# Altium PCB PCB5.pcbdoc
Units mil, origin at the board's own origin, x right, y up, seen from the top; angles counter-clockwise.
Board outline 5165.36 x 3350.39 mil, 2 copper layers (Top Layer, Bottom Layer); 78 components, 67 nets, 251 pads, 85 vias.
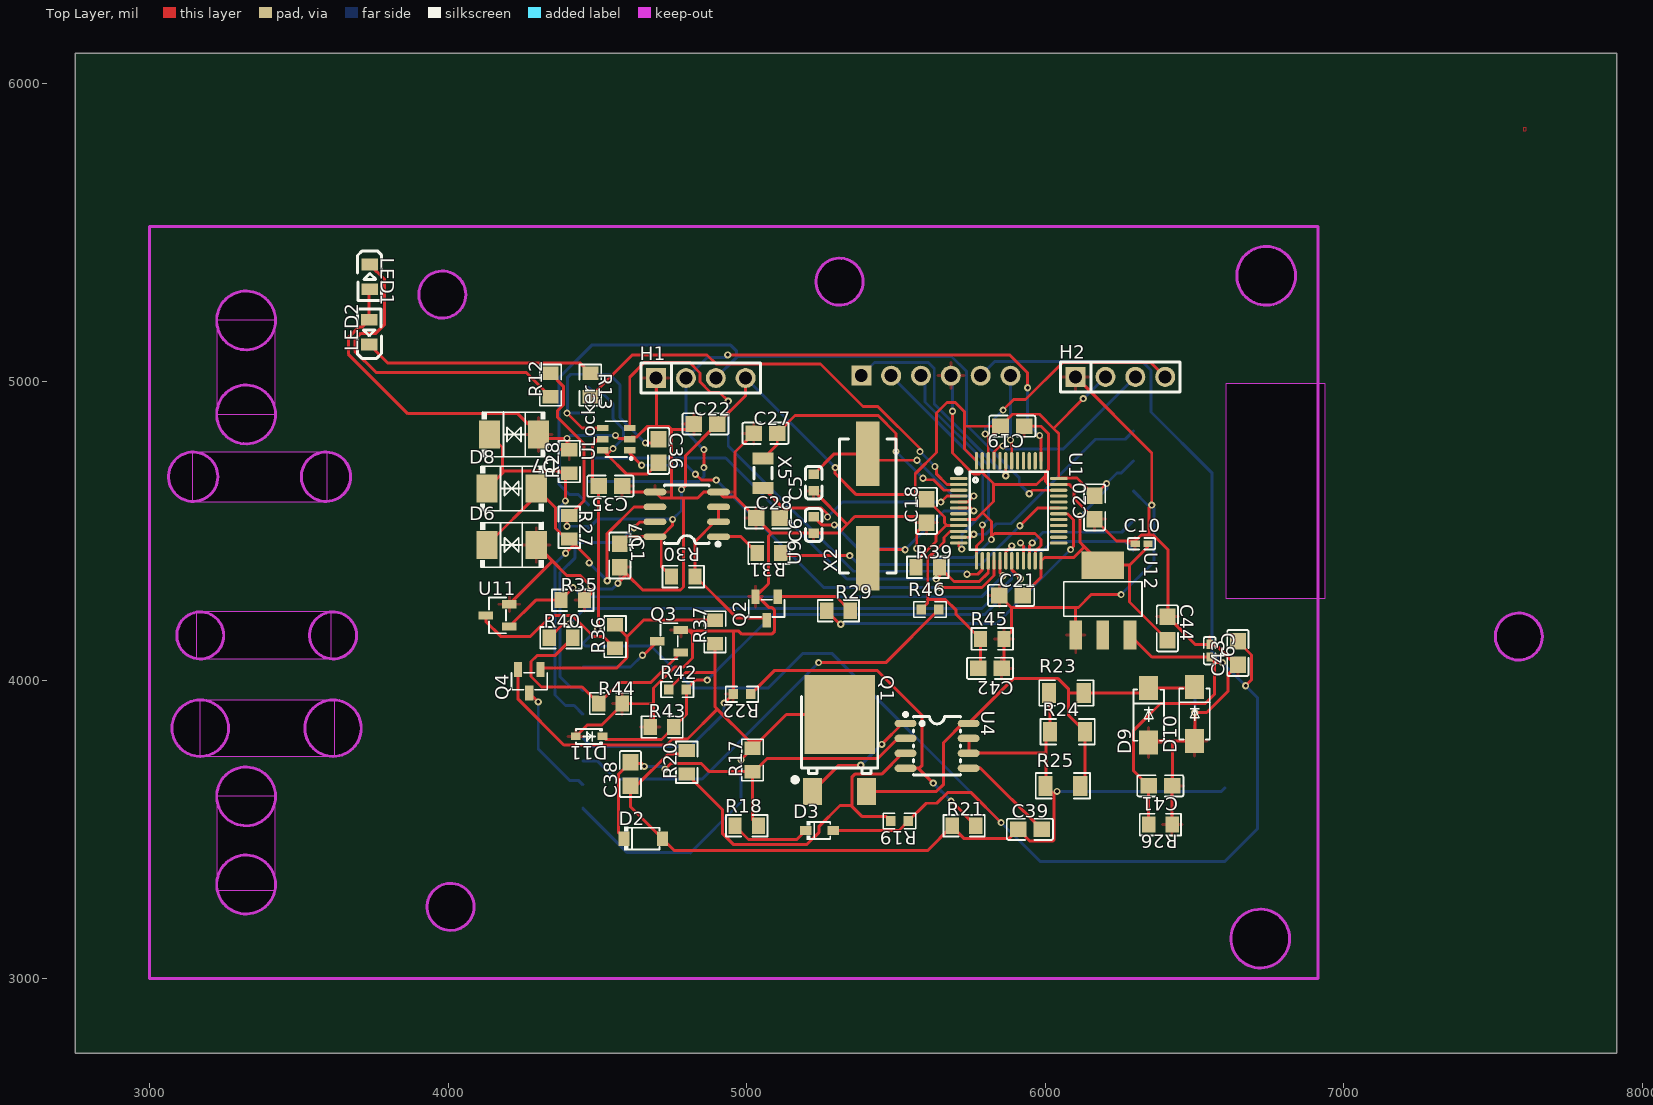
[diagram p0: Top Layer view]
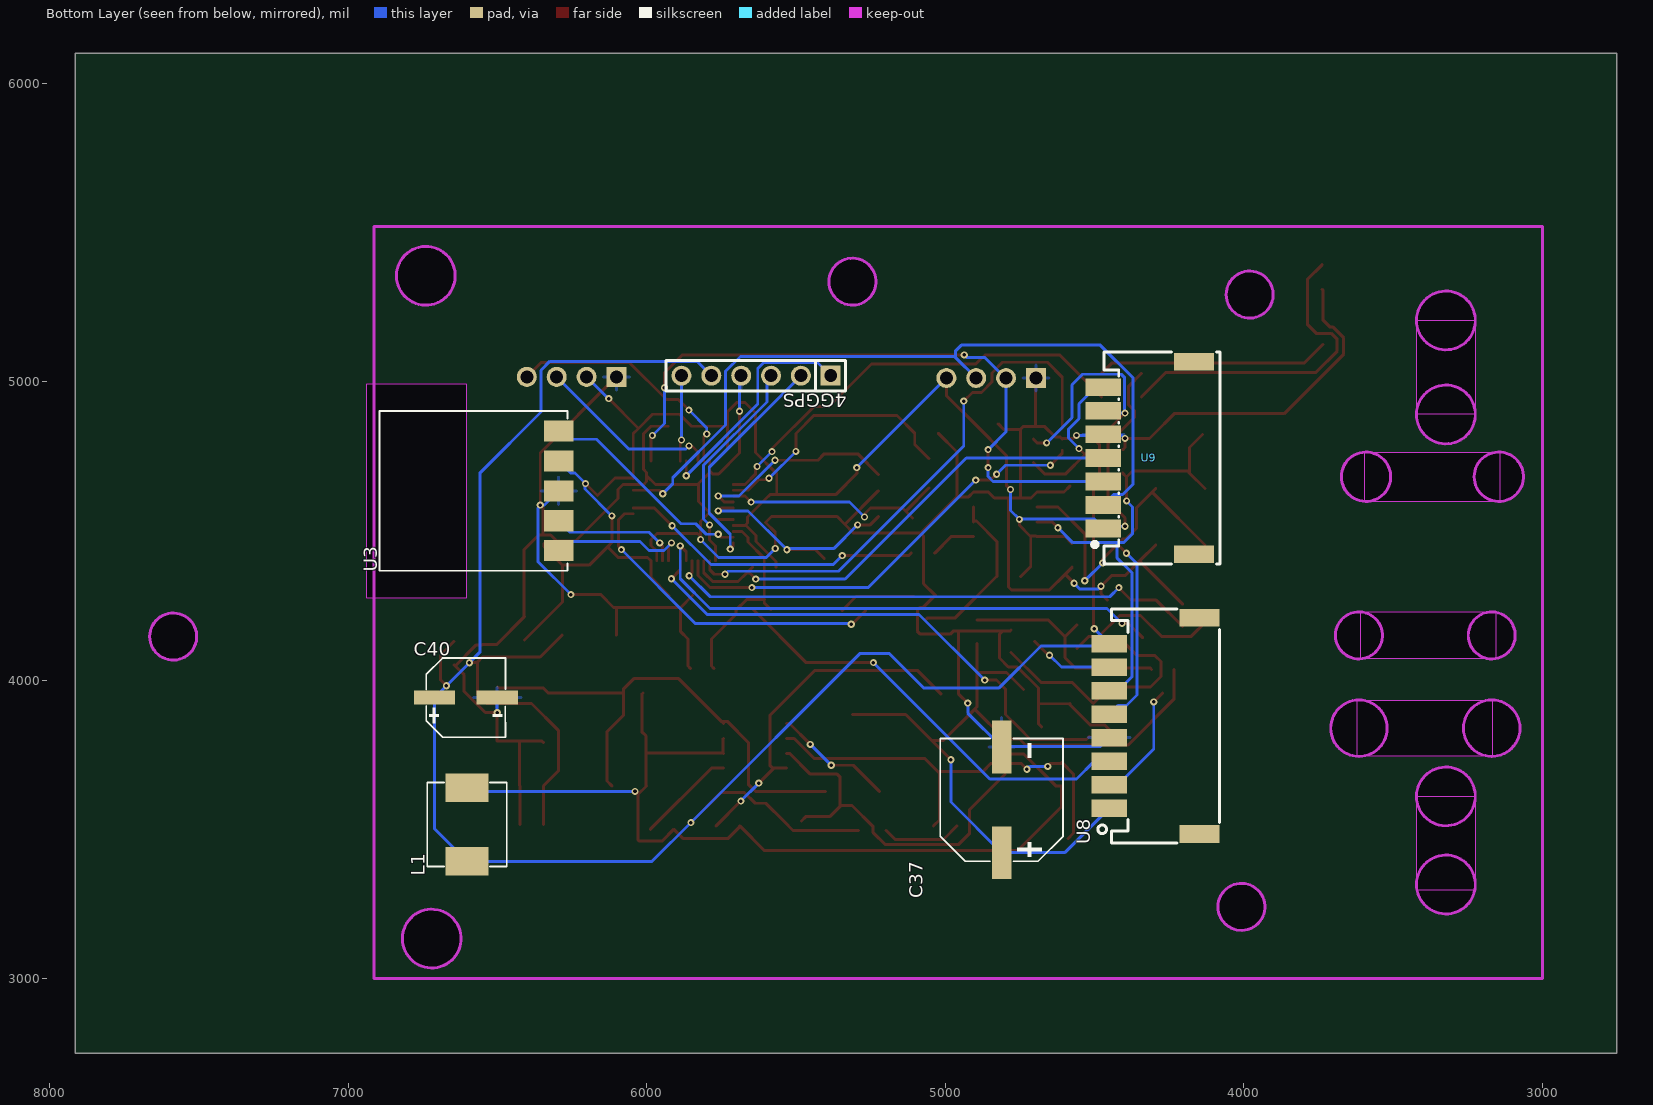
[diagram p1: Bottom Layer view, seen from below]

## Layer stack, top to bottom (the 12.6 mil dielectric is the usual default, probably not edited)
Top Layer: signal copper (thickness not stored)
Dielectric: dielectric 12.6, FR-4, Dk 4.8
Bottom Layer: signal copper (thickness not stored)

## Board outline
7915.36,2750 2750,2750 2750,6100.39 7915.36,6100.39
cut-out: 3421.26,4889.76 ccw(c3322.84,4889.56) 3224.41,4889.76 ccw(c3322.84,4889.96)
cut-out: 3421.26,3610.24 ccw(c3322.84,3610.04) 3224.41,3610.24 ccw(c3322.84,3610.44)
cut-out: 3421.26,5204.72 ccw(c3322.83,5204.48) 3224.41,5204.72 ccw(c3322.83,5204.97)
cut-out: 3421.26,3314.96 ccw(c3322.83,3314.72) 3224.41,3314.96 ccw(c3322.83,3315.2)
cut-out: 3673.23,4681.1 ccw(c3590.55,4681.1) 3507.87,4681.1 ccw(c3590.55,4681.1)
cut-out: 3692.91,4149.61 ccw(c3614.17,4149.61) 3535.43,4149.61 ccw(c3614.17,4149.61)
cut-out: 3708.66,3838.58 ccw(c3614.18,3837.9) 3519.69,3838.58 ccw(c3614.18,3839.26)
cut-out: 3228.35,4681.1 ccw(c3145.67,4681.1) 3062.99,4681.1 ccw(c3145.67,4681.1)
cut-out: 3263.78,3838.58 ccw(c3169.29,3838.58) 3074.8,3838.58 ccw(c3169.29,3838.58)
cut-out: 3248.03,4149.61 ccw(c3169.29,4149.61) 3090.55,4149.61 ccw(c3169.29,4149.61)
cut-out: 6838.58,5354.33 ccw(c6740.16,5354.33) 6641.73,5354.33 ccw(c6740.16,5354.33)
cut-out: 6818.9,3133.86 ccw(c6720.47,3133.6) 6622.05,3133.86 ccw(c6720.47,3134.12)
cut-out: 4059.06,5291.34 ccw(c3980.32,5290.73) 3901.58,5291.34 ccw(c3980.32,5291.95)
cut-out: 4086.61,3240.16 ccw(c4007.87,3240.16) 3929.13,3240.16 ccw(c4007.87,3240.16)
cut-out: 7665.36,4145.67 ccw(c7586.62,4145.14) 7507.88,4145.67 ccw(c7586.62,4146.19)
cut-out: 5389.77,5334.65 ccw(c5311.02,5334.65) 5232.28,5334.65 ccw(c5311.02,5334.65)
cut-out: 3224.41,4889.76 3421.26,4889.76 3421.26,5204.72 3224.41,5204.72
cut-out: 3224.41,3295.28 3421.26,3295.28 3421.26,3610.24 3224.41,3610.24
cut-out: 3141.73,4597.91 3594.49,4597.91 3594.49,4763.37 3141.73,4763.37
cut-out: 3155.51,4070.82 3608.27,4070.82 3608.27,4228.4 3155.51,4228.4
cut-out: 3167.32,3744.04 3620.08,3744.04 3620.08,3933.12 3167.32,3933.12
cut-out: 6604.87,4273.8 6938.98,4273.8 6938.98,4993.12 6604.87,4993.12

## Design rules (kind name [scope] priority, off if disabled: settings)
Clearance copperThickness1oz [All] p1: gap=7 ignorepadtopadclearanceinfootprint=FALSE except(4: Track-Track; 6: Track-SMDPad SMDPad-SMDPad Track-THPad SMDPad-THPad THPad-THPad Track-Via SMDPad-Via THPad-Via Via-Via SMDPad-Fill THPad-Fill Via-Fill Fill-Fill Track-Region SMDPad-Region THPad-Region Via-Region Region-Region Track-Poly SMDPad-Poly THPad-Poly Via-Poly Fill-Poly Region-Poly Poly-Poly Track-Text SMDPad-Text THPad-Text Via-Text Fill-Text Region-Text Poly-Text Text-Text; 6.9: Track-Hole SMDPad-Hole THPad-Hole Via-Hole Fill-Hole Region-Hole Poly-Hole Text-Hole Sheet-Hole; 11.8: Track-Fill Fill-Region Track-Sheet SMDPad-Sheet THPad-Sheet Via-Sheet Fill-Sheet Region-Sheet Poly-Sheet Text-Sheet)
Clearance copperThickness2oz [All] p1: gap=7 ignorepadtopadclearanceinfootprint=FALSE except(6: Track-SMDPad SMDPad-SMDPad Track-THPad SMDPad-THPad THPad-THPad Track-Via SMDPad-Via THPad-Via Via-Via SMDPad-Fill THPad-Fill Via-Fill Fill-Fill Track-Region SMDPad-Region THPad-Region Via-Region Region-Region Track-Poly SMDPad-Poly THPad-Poly Via-Poly Fill-Poly Region-Poly Poly-Poly Track-Text SMDPad-Text THPad-Text Via-Text Fill-Text Region-Text Poly-Text Text-Text; 6.9: Track-Hole SMDPad-Hole THPad-Hole Via-Hole Fill-Hole Region-Hole Poly-Hole Text-Hole Sheet-Hole; 8: Track-Track; 11.8: Track-Fill Fill-Region Track-Sheet SMDPad-Sheet THPad-Sheet Via-Sheet Fill-Sheet Region-Sheet Poly-Sheet Text-Sheet)
DiffPairsRouting differentialPair [All] p1: maxuncoupledlength=10 maxlimit=5.9843 mostfreqgap=5.9843 toplayer_minwidth=5 toplayer_prefwidth=10 toplayer_maxwidth=100 bottomlayer_minwidth=5 bottomlayer_prefwidth=10 bottomlayer_maxwidth=100
PasteMaskExpansion pasteMaskExpansion [All] p1:
PlaneConnect innerPlane [All] p1: planeconnectstyle=Relief reliefexpansion=20 reliefentries=4 reliefconductorwidth=10 reliefairgap=10
PolygonConnect copperRegion [All] p1: connectstyle=Relief reliefentries=4 reliefconductorwidth=10 polygonreliefangle="90 Angle" airgapwidth=10
RoutingVias viaSize [All] p1: viastyle="Through Hole" holewidth=12.0078 minholewidth=11.811 maxholewidth=248.0314 width=24.0158 minwidth=19.685 maxwidth=393.7008
SolderMaskExpansion solderMaskExpansion [All] p1: useseparateexpansions=TRUE expansion=2.0079 expansionbottom=2.0079
Width copperThickness1oz [All] p1: maxlimit=100 minlimit=5 preferedwidth=10
Width copperThickness2oz [All] p1: maxlimit=100 minlimit=8 preferedwidth=10

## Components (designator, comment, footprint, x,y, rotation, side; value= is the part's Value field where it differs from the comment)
4GGPS "X6511WV-06H-C60D30" HDR-TH_6P-P2.54-V-M 5633.86,5019.69 r0 bottom
C1 "CC0805KRX7R9BB104" C0805 4574.8,4417.32 r270 top
C5 "CL10C220JB8NNNC" C0603 5224.41,4661.42 r90 top
C6 "CL10C220JB8NNNC" C0603 5224.41,4519.69 r90 top
C9 "CL05A106MQ5NUNC" C0402 6551.18,4098.43 r270 top
C10 "CL05A106MQ5NUNC" C0402 6322.84,4456.69 r0 top
C18 "CC0805KRX7R9BB104" C0805 5602.36,4566.93 r90 top
C19 "CC0805KRX7R9BB104" C0805 5889.77,4850.39 r180 top
C20 "CC0805KRX7R9BB104" C0805 6165.36,4578.74 r90 top
C21 "CC0805KRX7R9BB104" C0805 5885.83,4283.46 r0 top
C22 "CC0805KRX7R9BB104" C0805 4862.21,4858.27 r0 top
C27 "0805CG120J500NT" C0805 5062.99,4826.77 r0 top
C28 "0805CG120J500NT" C0805 5070.87,4543.31 r0 top
C35 "CL21A475KAQNNNE" C0805 4543.31,4649.61 r180 top
C36 "CC0805KRX7R9BB104" C0805 4704.73,4767.72 r270 top
C37 "RVT2A470M1010_C335988" CAP-SMD_BD10.0-L10.3-W10.3-LS11.3-FD 4811.02,3598.42 r90 bottom
C38 "CL21A225KBQNNNE" C0805 4610.24,3685.04 r90 top
C39 "CL21A475KAQNNNE" C0805 5948.82,3500 r0 top
C40 "RVT220UF16V67RV0015" CAP-SMD_BD6.3-L6.6-W6.6-FD 6606.3,3940.94 r180 bottom
C41 "CC0805KRX7R9BB104" C0805 6385.83,3645.67 r180 top
C42 "CC0805KRX7R9BB104" C0805 5814.96,4039.37 r180 top
C43 "CC0805KRX7R9BB104" C0805 6645.67,4090.55 r90 top
C44 "CC0805KRX7R9BB104" C0805 6409.45,4173.23 r270 top
D2 "BZT52B12_C22395569" SOD-123_L2.7-W1.6-LS3.7-RD 4653.54,3468.5 r0 top
D3 "1N4148WS_C2128" SOD-323_L1.8-W1.3-LS2.5-RD 5244.1,3496.06 r0 top
D6 "SMBJ6.5CA_C7420377" SMB_L4.6-W3.5-LS5.3-BI 4212.6,4452.76 r0 top
D7 "SMBJ6.5CA_C7420377" SMB_L4.6-W3.5-LS5.3-BI 4220.47,4822.83 r180 top
D8 "SMBJ6.5CA_C7420377" SMB_L4.6-W3.5-LS5.3-BI 4212.6,4641.73 r0 top
D9 "SS310_C7420364" SMA_L4.3-W2.6-LS5.0-FD 6346.46,3881.89 r90 top
D10 "SS310_C7420364" SMA_L4.3-W2.6-LS5.0-FD 6500,3885.83 r90 top
D11 "BZT52C3V3S_C19077437" SOD-323_L1.7-W1.3-LS2.6-RD 4472.44,3811.02 r180 top
H1 "HDR-M_2.54_1x4P" HDR-TH_4P-P2.54-V-M 4846.46,5011.81 r0 top
H2 "HDR-M_2.54_1x4P" HDR-TH_4P-P2.54-V-M 6251.97,5015.75 r0 top
L1 "FXL0630-470-M" IND-SMD_L7.0-W6.6_FXL0630 6602.36,3515.75 r90 bottom
LED1 "NCD0805R1" LED0805-R-RD 3737.32,5350.39 r270 top
LED2 "KT-0805G" LED0805-R-RD 3735.32,5165.35 r90 top
Q1 "TX15N10B" TO-252_L6.5-W6.1-P4.58-LS9.9-BR 5311.02,3755.91 r270 top
Q2 "SS8050_C7420370" SOT-23-3_L2.9-W1.3-P1.90-LS2.4-BR 5066.93,4240.16 r90 top
Q3 "SS8050_C7420370" SOT-23-3_L2.9-W1.3-P1.90-LS2.4-BR 4740.16,4129.92 r0 top
Q4 "PJM10H01PSA" SOT-23-3_L2.9-W1.3-P0.95-LS2.4-BR 4271.65,3996.06 r90 top
R12 "0805W8F1001T5E" R0805 4342.52,4988.19 r90 top
R13 "0805W8F1001T5E" R0805 4476.38,4988.19 r270 top
R17 "0805W8F5102T5E" R0805 5019.69,3732.28 r90 top
R18 "0805W8F1000T5E" R0805 5000,3511.81 r0 top
R19 "0603WAF6202T5E" R0603 5511.81,3527.56 r180 top
R20 "0805W8F4991T5E" R0805 4799.21,3724.41 r90 top
R21 "0805W8F4991T5E" R0805 5728.35,3511.81 r0 top
R22 "0603WAF6202T5E" R0603 4984.25,3952.76 r180 top
R23 "1206W4F100LT5E" R1206 6070.87,3956.69 r0 top
R24 "1206W4F100LT5E" R1206 6074.8,3826.77 r0 top
R25 "1206W4F100LT5E" R1206 6059.06,3645.67 r0 top
R26 "0805W8F2201T5E" R0805 6385.83,3515.75 r180 top
R27 "0805W8F4701T5E" R0805 4405.51,4511.81 r270 top
R28 "0805W8F4701T5E" R0805 4405.51,4732.28 r90 top
R29 "0805W8F4701T5E" R0805 5307.09,4232.28 r0 top
R30 "0805W8F4701T5E" R0805 4787.4,4346.46 r180 top
R31 "0805W8F1001T5E" R0805 5074.8,4425.2 r180 top
R35 "0805W8F1002T5E_C17414" R0805 4417.32,4267.72 r0 top
R36 "0805W8F5102T5E" R0805 4559.06,4145.67 r90 top
R37 "0805W8F1002T5E_C17414" R0805 4893.7,4161.42 r90 top
R39 "0805W8F1002T5E_C17414" R0805 5606.3,4377.95 r0 top
R40 "0805W8F4701T5E" R0805 4377.95,4141.73 r0 top
R42 "0603WAF6202T5E" R0603 4767.72,3968.5 r0 top
R43 "0805W8F2001T5E" R0805 4716.54,3842.52 r0 top
R44 "0805W8F1002T5E_C17414" R0805 4543.31,3921.26 r0 top
R45 "0805W8F1002T5E_C17414" R0805 5822.84,4137.8 r0 top
R46 "0603WAF0000T5E" R0603 5614.17,4236.22 r0 top
U1 "STM32F103C8T6" LQFP-48_L7.0-W7.0-P0.50-LS9.0-BL 5877.95,4566.93 r270 top
U3 "VG6328A" COMM-SMD_VG6328A 6295.28,4633.86 r90 bottom
U4 "TX4131L_C19192514" SOP-8_L4.9-W3.9-P1.27-LS6.0-BL 5637.8,3779.53 r270 top
U7 "SP3485EN-L/TR" SOIC-8_L5.0-W4.0-P1.27-LS6.0-BL 4799.21,4555.12 r90 top
U8 "ZX-HY2.0-8PWT" CONN-SMD_8P-P2.00_WAFER-HY2.0-8PWB 4299.21,3846.46 r90 bottom
U9 "ZX-HY2.0-7PWT" CONN-SMD_7P-P2.00_ZX-HY2.0-7PWT 4318.9,4744.09 r90 bottom
U11 "BSS123_C7420338" SOT-23-3_L2.9-W1.3-P1.90-LS2.4-BR 4165.35,4216.54 r0 top
U12 "AMS1117-3.3_C6186" SOT-223-3_L6.5-W3.4-P2.30-LS7.0-BR 6192.92,4267.72 r270 top
ULocker "T1016H" SOT-23-6_L2.9-W1.7-P0.95-LS2.8-BL 4562.99,4807.09 r90 top
X2 "X49SM8MSD2SC" CRYSTAL-SMD_L11.5-W4.8-LS12.7 5405.51,4582.68 r90 top
X5 "Q13FC13500004_C32346" FC-135R_L3.2-W1.5 5055.12,4692.91 r270 top

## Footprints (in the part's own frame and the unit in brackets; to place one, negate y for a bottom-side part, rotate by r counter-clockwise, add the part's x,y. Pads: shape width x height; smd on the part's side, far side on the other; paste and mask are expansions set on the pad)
C0402 [mm]
  rect 0.79x0.54 smd: 1(-0.545,0) 2(0.545,0)
  silkscreen extent -1.17,-0.5 1.17,0.5
C0603 [mm]
  rect 0.8x0.9 smd: 1(-0.7,0) 2(0.7,0)
  silkscreen extent -1.41,-0.71 1.39,0.72
C0805 [mm]
  rect 1.41x1.35 smd: 1(-1,0) 2(1,0)
  silkscreen extent -1.96,-0.9 1.96,0.9
CAP-SMD_BD6.3-L6.6-W6.6-FD [mm]
  rect 3.5x1.2 smd: 1(-2.67,0) 2(2.67,0)
  silkscreen extent -3.38,-3.38 3.38,3.38
CAP-SMD_BD10.0-L10.3-W10.3-LS11.3-FD [mm]
  rect 4.5x1.65 smd: 1(-4.5,0) 2(4.5,0)
  silkscreen extent -5.23,-5.23 5.23,5.23
COMM-SMD_VG6328A [mm]
  rect 1.8x2.5 smd: 1(-5.08,0) 2(-2.54,0) 3(0,0) 4(2.54,0) 5(5.08,0)
  silkscreen extent -6.8,-0.75 6.8,15.25
CONN-SMD_7P-P2.00_ZX-HY2.0-7PWT [mm]
  rect 1.5x3 smd: 1(-6,3.85) 2(-4,3.85) 3(-2,3.85) 4(0,3.85) 5(2,3.85) 6(4,3.85) 7(6,3.85)
  rect 1.5x3.4 smd: 8(8.2,-3.85) 9(-8.2,-3.85)
  silkscreen extent -9.02,-6.1 9.02,4.77
CONN-SMD_8P-P2.00_WAFER-HY2.0-8PWB [mm]
  rect 1.5x3 smd: 1(-7,3.85) 2(-5,3.85) 3(-3,3.85) 4(-1,3.85) 5(1,3.85) 6(3,3.85) 7(5,3.85) 8(7,3.85)
  rect 1.5x3.4 smd: 9(-9.2,-3.85) 10(9.2,-3.85)
  silkscreen extent -9.95,-5.55 9.95,4.82
CRYSTAL-SMD_L11.5-W4.8-LS12.7 [mm]
  rect 5.5x2 smd: 1(-4.45,0) 2(4.45,0)
  silkscreen extent -5.7,-2.4 5.7,2.4
FC-135R_L3.2-W1.5 [mm]
  rect 1x1.8 smd: 1(-1.25,0) 2(1.25,0)
  silkscreen extent -0.51,-0.76 0.51,0.76
HDR-TH_4P-P2.54-V-M [mm]
  rect 1.7x1.7 hole 1.1: 1(-3.81,0)
  round 1.7 hole 1.1: 2(-1.27,0) 3(1.27,0) 4(3.81,0)
  silkscreen extent -5.08,-1.27 5.08,1.27
HDR-TH_6P-P2.54-V-M [mm]
  rect 1.7x1.7 hole 1.1: 1(-6.35,0)
  round 1.7 hole 1.1: 2(-3.81,0) 3(-1.27,0) 4(1.27,0) 5(3.81,0) 6(6.35,0)
  silkscreen extent -7.6,-1.3 7.65,1.3
IND-SMD_L7.0-W6.6_FXL0630 [mm]
  rect 2.424x3.62 smd: 1(3.128,0) 2(-3.128,0)
  silkscreen extent -3.58,-3.38 3.58,3.38
LED0805-R-RD [mm]
  rect 1x1.4 smd: 1(1.05,0) 2(-1.05,0)
  silkscreen extent -2.22,-1.04 1.99,1.01
LQFP-48_L7.0-W7.0-P0.50-LS9.0-BL [mm]
  oval 0.27x1.5 smd: 1(-2.75,-4.25) 2(-2.25,-4.25) 3(-1.75,-4.25) 4(-1.25,-4.25) 5(-0.75,-4.25) 6(-0.25,-4.25) 7(0.25,-4.25) 8(0.75,-4.25) 9(1.25,-4.25) 10(1.75,-4.25) 11(2.25,-4.25) 12(2.75,-4.25) 25(2.75,4.25) 26(2.25,4.25) 27(1.75,4.25) 28(1.25,4.25) 29(0.75,4.25) 30(0.25,4.25) 31(-0.25,4.25) 32(-0.75,4.25) 33(-1.25,4.25) 34(-1.75,4.25) 35(-2.25,4.25) 36(-2.75,4.25)
  oval 1.5x0.27 smd: 13(4.25,-2.75) 14(4.25,-2.25) 15(4.25,-1.75) 16(4.25,-1.25) 17(4.25,-0.75) 18(4.25,-0.25) 19(4.25,0.25) 20(4.25,0.75) 21(4.25,1.25) 22(4.25,1.75) 23(4.25,2.25) 24(4.25,2.75) 37(-4.25,2.75) 38(-4.25,2.25) 39(-4.25,1.75) 40(-4.25,1.25) 41(-4.25,0.75) 42(-4.25,0.25) 43(-4.25,-0.25) 44(-4.25,-0.75) 45(-4.25,-1.25) 46(-4.25,-1.75) 47(-4.25,-2.25) 48(-4.25,-2.75)
  silkscreen extent -3.59,-4.46 3.3,3.34
R0603 [mil]
  rect 31.75x34.02 smd: 1(-29.66,0) 2(29.66,0)
  silkscreen extent -55,-26 55,26
R0805 [mm]
  rect 1.133x1.377 smd: 1(-1,0) 2(1,0)
  silkscreen extent -1.76,-0.92 1.76,0.92
R1206 [mil]
  rect 47.54x66.97 smd: 1(-58.22,0) 2(58.22,0)
  silkscreen extent -91,-42 91,42
SMA_L4.3-W2.6-LS5.0-FD [mm]
  rect 2.046x1.62 smd: 1(-2.304,-0.009) 2(2.304,0.009)
  silkscreen extent -2.17,-1.32 2.19,1.29
SMB_L4.6-W3.5-LS5.3-BI [mm]
  rect 1.8x2.4 smd: 1(-2.091,0) 2(2.091,0)
  silkscreen extent -2.68,-1.91 2.75,1.91
SOD-123_L2.7-W1.6-LS3.7-RD [mm]
  rect 0.91x1.22 smd: 1(-1.635,0) 2(1.635,0)
  silkscreen extent -1.6,-1 1.38,1
SOD-323_L1.7-W1.3-LS2.6-RD [mm]
  rect 0.83x0.63 smd: 1(-1.14,0) 2(1.14,0)
  silkscreen extent -1.08,-0.64 1.13,0.64
SOD-323_L1.8-W1.3-LS2.5-RD [mm]
  rect 1x0.75 smd: 1(-1.173,0) 2(1.173,0)
  silkscreen extent -1.08,-0.8 0.9,0.8
SOIC-8_L5.0-W4.0-P1.27-LS6.0-BL [mil]
  oval 22.38x76.78 smd: 1(-75,-106.5) 2(-25,-106.5) 3(25,-106.5) 4(75,-106.5) 5(75,106.5) 6(25,106.5) 7(-25,106.5) 8(-75,106.5)
  silkscreen extent -106,-111 98,75
SOP-8_L4.9-W3.9-P1.27-LS6.0-BL [mm]
  oval 0.63x1.865 smd: 1(-1.905,-2.682) 2(-0.635,-2.682) 3(0.635,-2.682) 4(1.905,-2.682) 5(1.905,2.682) 6(0.635,2.682) 7(-0.635,2.682) 8(-1.905,2.682)
  silkscreen extent -2.82,-2.83 2.5,2
SOT-23-3_L2.9-W1.3-P0.95-LS2.4-BR [mm]
  rect 1.25x0.7 smd: 1(1,-0.95) 2(1,0.95) 3(-1,0)
  silkscreen extent -0.73,-1.53 0.73,1.53
SOT-23-3_L2.9-W1.3-P1.90-LS2.4-BR [mm]
  rect 1.25x0.7 smd: 1(1,-0.95) 2(1,0.95) 3(-1,0)
  silkscreen extent -0.73,-1.53 0.73,1.53
SOT-23-6_L2.9-W1.7-P0.95-LS2.8-BL [mm]
  rect 0.532x0.99 smd: 1(-0.95,-1.145) 2(0,-1.145) 3(0.95,-1.145) 4(0.95,1.145) 5(0,1.145) 6(-0.95,1.145)
  silkscreen extent -1.75,-1.37 1.53,0.93
SOT-223-3_L6.5-W3.4-P2.30-LS7.0-BR [mm]
  rect 2.5x1.1 smd: 1(2.97,-2.3) 2(2.97,0) 3(2.97,2.3)
  rect 2.34x3.6 smd: 4(-2.97,0)
  silkscreen extent -1.57,-3.33 1.37,3.33
TO-252_L6.5-W6.1-P4.58-LS9.9-BR [mm]
  rect 2.3x1.6 smd: 1(3.268,-2.29) 3(3.267,2.29)
  rect 6.7x6 smd: 2(-3.268,0)
  silkscreen extent -4.79,-3.98 2.49,3.25

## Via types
v1: diameter 24.02, hole 12.01, Top Layer to Bottom Layer, 85 vias

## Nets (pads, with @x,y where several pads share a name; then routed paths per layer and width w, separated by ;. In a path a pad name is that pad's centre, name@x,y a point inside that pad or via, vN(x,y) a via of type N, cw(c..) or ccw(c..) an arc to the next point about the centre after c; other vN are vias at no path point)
3V3: C1.1 C10.2 C18.2 C19.2 C20.2 C21.2 C22.2 C44.2 H1.4 H2.2 R12.2 R27.1 R30.2 R39.1 U1.9 U1.24 U1.36 U1.48 U3.4 U7.8 U9.1 U12.4 | length 5876
  Top Layer w9.57: 5564.67,4621.1 5564.67,4691.1 5635.38,4761.81 5635.38,4894.96 5670.73,4930.32 5698.6,4930.32 5730.02,4898.89 5730.02,4848.67 ; R39.1 5566.93,4397.34 5633.77,4464.18 5633.77,4484.18 5669.13,4519.53 ; C18.2 5662.36,4546.3 5662.36,4526.3 5669.13,4519.53 ; U1.9 5670.94,4517.72 5669.13,4519.53 ; U1.48 5730.02,4773.91 5730.02,4848.67 ; C21.2 5986.22,4344.49 U1.24 5997.55,4410.94 6095.91,4410.94 6131.27,4446.29 ; U1.36 U1.36@6045.27,4677.23 ; C20.2 6106.24,4677.23 U1.36@6045.27,4677.23 ; 5730.02,4848.67 5731.75,4850.39 C19.2 5890.4,4890.39 5980.4,4890.39 6027.75,4843.04 6045.27,4825.52 U1.36@6045.27,4677.23
  Top Layer w10: R12.2 4385.51,4984.57 4385.51,4921.18 4365.51,4901.18 4365.51,4881.18 4455.51,4791.18 4455.51,4601.18 R27.1 4397.83,4543.5 v1(4397.83,4515.23) ; C1.1 4599.26,4481.14 U7.8@4693.74,4481.14 ; U7.8 U7.8@4693.74,4481.14 ; R30.2 4713.72,4380.77 U7.8@4713.72,4482.91 ; v1(4751.58,4538.27) 4751.58,4518.27 4716.22,4482.91 U7.8@4713.72,4482.91 ; v1(4781.58,4638.27) 4795.51,4652.2 4795.51,4752.2 C22.2 4996.46,4953.15 H1.4 ; v1(5296.46,4711.81) 5296.46,4691.81 5367.17,4621.1 5564.67,4621.1 5587.56,4621.1 C18.2 ; 6027.75,4843.04 v1(6127.75,4943.04) ; v1(6117.12,4549.88) 6117.12,4460.44 6131.27,4446.29 U12.4 6282.25,4384.64 ; C20.2 v1(6205.36,4658.11) ; C10.2 6344.3,4446.69 6282.25,4384.64 ; C44.2 6282.25,4261.06 6282.25,4384.64 ; U7.8@4693.74,4481.14 4695.51,4482.91 U7.8@4713.72,4482.91
  Bottom Layer w10: v1(4397.83,4515.23) U9.1@4477.83,4515.23 ; U9.1 U9.1@4477.83,4515.23 ; v1(4751.58,4538.27) v1@4753.29,4539.98 ; v1(4781.58,4638.27) 4781.58,4568.27 v1@4753.29,4539.98 ; H1.4 v1(5296.46,4711.81) ; v1(6117.12,4549.88) 6207.12,4639.88 v1@6207.12,4659.88 ; v1(6127.75,4943.04) 6129.26,4943.04 H2.2 ; v1(6205.36,4658.11) v1@6207.12,4659.88 ; U3.4 6254.89,4693.47 6240.71,4693.47 v1@6207.12,4659.88 ; U9.1@4477.83,4515.23 4502.58,4539.98 v1@4753.29,4539.98
485A: D6.1 D8.2 R27.2 U7.6 U8.5 | length 1670.9
  Top Layer w10: D6.1 4305.36,4627.85 D8.2@4305.36,4631.32 ; D8.2 D8.2@4305.36,4631.32 ; v1(4393.22,4424.74) R27.2@4423.22,4454.74 ; v1(4472.71,4392.44) 4472.71,4405.24 R27.2@4423.22,4454.74 ; v1(4532.71,4332.44) 4532.71,4490.12 4622.71,4580.12 U7.6 ; D8.2@4305.36,4631.32 4360.16,4576.51 4360.16,4507.8 4395.51,4472.44 R27.2 R27.2@4423.22,4454.74
  Bottom Layer w10: v1(4393.22,4424.74) 4357.86,4389.38 4357.86,3950.09 4393.22,3914.74 4421.87,3914.74 U8.5 ; v1(4472.71,4392.44) v1(4532.71,4332.44)
485B: D7.2 D8.1 R28.1 U7.7 U8.6 | length 1585.7
  Top Layer w10: D8.1 4181.57,4693.04 ; D7.2 4181.57,4779.4 4181.57,4693.04 ; v1(4392.71,4600.12) R28.1@4392.71,4680.11 ; R28.1 R28.1@4392.71,4680.11 ; v1(4622.71,4510.12) 4642.71,4530.12 U7.7 ; 4181.57,4693.04 4188.64,4700.11 4372.71,4700.11 R28.1@4392.71,4680.11
  Bottom Layer w10: v1(4392.71,4600.12) 4372.71,4580.12 4372.71,4490.12 4402.71,4460.12 4425.21,4460.12 ; U8.6 4440.57,3974.78 4410.57,3974.78 4375.21,4010.14 4375.21,4360.12 4425.21,4410.12 4425.21,4460.12 ; v1(4622.71,4510.12) 4572.71,4460.12 4425.21,4460.12
$1N2074: LED1.2 R12.1 | length 1100
  Top Layer w10: LED1.2 3787.32,5341.74 3787.32,5191.74 3757.32,5161.74 3707.32,5161.74 3687.32,5141.74 3687.32,5101.74 3758.03,5031.03 4260.31,5031.03 R12.1
$1N2077: LED2.2 R13.1 | length 781
  Top Layer w10: LED2.2 3796.41,5062.91 4441.02,5062.91 R13.1
$4N4676: C39.2 U4.5 | length 329.5
  Top Layer w10: U4.5 5783.66,3704.53 C39.2
$4N4693: R19.2 R20.1 U4.3 | length 1223.8
  Top Layer w10: R20.1 4919.37,3564.88 4919.37,3484.88 4954.73,3449.53 5202.19,3449.53 5241.48,3488.82 5241.48,3508.82 5312.19,3579.53 5352.19,3579.53 ; R19.2 5467.54,3542.17 5387.54,3542.17 5352.19,3577.52 5352.19,3579.53 ; U4.3 5522.19,3754.53 5452.19,3684.53 5362.19,3684.53 5352.19,3674.53 5352.19,3579.53
$4N4698: 
$4N4701: R21.2 R22.1 U4.4 | length 1167.6
  Top Layer w10: R22.1 5093.91,4032.76 5436.77,4032.76 5586.77,3882.76 5586.77,3712.76 5576.77,3702.76 ; U4.4 5575,3704.53 5576.77,3702.76 ; v1(5625,3654.53) 5576.77,3702.76 ; v1(5685,3594.53) R21.2
  Bottom Layer w10: v1(5625,3654.53) v1(5685,3594.53)
$4N4703: C38.2 D2.1 R17.1 R18.2 U4.2 | length 1471.5
  Top Layer w10: D2.1 4570.24,3487.44 4570.24,3684.41 C38.2@4606.7,3720.87 ; C38.2 C38.2@4606.7,3720.87 ; v1(4656.7,3710.87) 4646.7,3720.87 C38.2@4606.7,3720.87 ; v1(4726.7,3700.87) 4746.7,3720.87 4846.7,3720.87 4874.66,3692.91 R17.1 R17.1@5019.69,3687.91 ; R18.2 5019.69,3531.5 R17.1@5019.69,3687.91 ; U4.2 5506.3,3804.53 5439.69,3737.91 5069.69,3737.91 R17.1@5019.69,3687.91
  Bottom Layer w10: v1(4656.7,3710.87) 4716.7,3710.87 v1(4726.7,3700.87)
$4N4719: D3.1 R18.1 | length 268.7
  Top Layer w10: R18.1 5006.38,3466.06 5167.93,3466.06 D3.1
$4N4723: D9.2 D10.2 Q1.3 R23.2 R24.2 R25.2 U4.8 | length 1722.1
  Top Layer w10: Q1.3 5636.16,3627.28 5659.77,3650.89 5659.77,3790.89 5730.48,3861.6 U4.8@5750.48,3861.6 ; U4.8 U4.8@5750.48,3861.6 ; 6078.76,3956.69 R23.2 6330.19,3956.69 D9.2 6495.69,3972.59 D10.2 ; R25.2 6133.02,3661.42 R24.2 6078.76,3881.03 6078.76,3956.67 6078.76,3969.17 6043.41,4004.53 5893.41,4004.53 U4.8@5750.48,3861.6
$6N472: Q2.3 R30.1 U7.2 U7.3 | length 576.1
  Top Layer w10: R30.1 R30.1@4826.77,4348.68 ; U7.2 U7.2@4905.71,4532.62 ; U7.3 U7.2@4905.71,4532.62 ; Q2.3 5060.46,4207.26 4968.19,4207.26 R30.1@4826.77,4348.68 ; R30.1@4826.77,4348.68 4826.77,4463.68 4895.71,4532.62 U7.2@4905.71,4532.62
$6N475: R31.2 U7.1 | length 152.5
  Top Layer w10: U7.1 4980.51,4480.12 R31.2
$6N478: Q2.1 R29.2 | length 261.7
  Top Layer w10: Q2.1 5299.21,4279.53 R29.2
$8N894: Q4.1 R36.2 R37.2 | length 750.7
  Top Layer w10: Q4.1 4313.31,4039.68 4563.7,4039.68 4599.06,4075.04 4599.06,4145.04 ; R36.2 4599.06,4145.04 ; R37.2 4654.8,4200.79 4599.06,4145.04
$8N1397: R36.1 U11.3 | length 548.4
  Top Layer w10: U11.3 4125.98,4196.54 4175.98,4146.54 4275.98,4146.54 4345.98,4216.54 4415.98,4216.54 4486.7,4145.82 4519.53,4145.82 R36.1
$11N115: Q3.1 R40.2 R44.1 | length 833.8
  Top Layer w10: R40.2 4357.32,4081.73 4297.32,4081.73 4277.32,4061.73 4277.32,4011.73 4312.68,3976.38 4448.82,3976.38 R44.1 4574.65,3991.97 4678.98,3991.97 Q3.1
+5V: 4GGPS.5 C9.2 C35.2 C40.1 C41.2 C43.2 D3.2 L1.2 R19.1 R26.2 U8.8 U12.3 ULocker.5 | length 7677.4
  Top Layer w10: v1(4500.79,4172.04) 4503.94,4175.19 C35.2 4483.94,4669.61 4483.94,4789.61 4501.42,4807.09 ULocker.5 ; D3.2 5509.98,3496.06 R19.1 5601.16,3587.24 5637.01,3587.24 5672.36,3622.6 5752.36,3622.6 v1(5852.36,3522.6) ; U12.3 6357.29,4076.97 C9.2 6566.54,4061.6 ; R26.2 C41.2 6296.54,3695.58 6296.54,3831.6 6386.54,3921.6 6536.54,3921.6 6566.54,3951.6 6566.54,4061.6 ; v1(6594.3,4058.07) 6570.08,4058.07 6566.54,4061.6 ; C43.2 6691.42,4084.17 6691.42,4000.94 v1(6671.42,3980.94)
  Bottom Layer w10: v1(4500.79,4172.04) U8.8 4458.81,4114.02 4679.57,4114.02 4820.99,3972.6 5070.99,3972.6 5186.68,4088.28 5286.68,4088.28 v1(5852.36,3522.6) 5982.36,3392.6 L1.2 6711.42,3501.65 C40.1 v1(6671.42,3980.94) v1(6594.3,4058.07) 6559.39,4092.97 6559.39,4692.97 6354.75,4897.62 6354.75,5037.62 6324.75,5067.62 5831.79,5067.62 4GGPS.5
AGND: C38.1 C39.1 D2.2 L1.1 R20.2 R21.1 R23.1 R24.1 R25.1 U4.6 U4.7 | length 3276.7
  Top Layer w10: R20.2 4787.17,3751.74 4736.3,3751.74 4630.24,3645.67 C38.1 4610.24,3576.18 D2.2 4757.92,3428.5 5605.67,3428.5 R21.1@5686.99,3509.82 ; R21.1 R21.1@5686.99,3509.82 ; U4.6 5744.95,3756.07 U4.6@5745.43,3756.07 ; U4.7 5745.43,3802.5 U4.6@5745.43,3756.07 ; R25.1 R25.1@6002.93,3643.57 ; R23.1 6016.58,3952.76 R24.1 6002.93,3813.12 6002.93,3756.07 ; v1(6039.45,3627.06) 6029.45,3617.06 ; R21.1@5686.99,3509.82 5726.99,3469.82 5879.27,3469.82 C39.1 5949.45,3460 6025.11,3460 6029.45,3464.34 6029.45,3617.06 ; U4.6@5745.43,3756.07 6002.93,3756.07 ; R25.1@6002.93,3643.57 6029.45,3617.06 ; R25.1@6002.93,3643.57 6002.93,3756.07
  Bottom Layer w10: v1(6039.45,3627.06) 6590.52,3627.06 L1.1
BOOT0: U1.44
BOOT1: U1.20
DIANMEN: Q4.3 U8.2 | length 398.9
  Top Layer w10: Q4.3 v1(4301.65,3926.69)
  Bottom Layer w10: v1(4301.65,3926.69) 4301.65,3768.74 4407.72,3662.67 4437.72,3662.67 U8.2
GND: 4GGPS.4 C1.2 C5.1 C6.1 C9.1 C10.1 C18.1 C19.1 C20.1 C21.1 C22.1 C27.1 C28.1 C35.1 C37.2 C40.2 C41.1 C42.1 C43.1 C44.1 D6.2 D7.1 D9.1 D10.1 D11.2 H1.1 H2.1 LED1.1 LED2.1 Q2.2 Q3.2 R22.2 R26.1 R28.2 R35.2 R43.1 R44.2 R45.2 U1.8 U1.23 U1.35 U1.47 U3.3 U7.4 U7.5 U8.4 U9.5 U11.2 U12.1 ULocker.2 | length 12578
  Top Layer w9.57: v1(5569.93,4440.82) 5569.93,4495.12 C18.1 ; U1.8 5766.51,4537.4 5789.93,4560.82 ; U1.47 5789.37,4700.57 5789.37,4695.78 5827.13,4658.03 ; v1(5819.93,4470.82) v1@5819.93,4480.59 ; C21.1 5886.46,4243.46 6101.89,4243.46 6111.91,4243.46 6154.51,4286.06 v1(6254.51,4286.06) ; C19.1 5985.63,4850.39 6010.52,4825.51 6010.52,4705.51 6000.52,4695.51 6000.52,4684.64 ; U1.23 5966.53,4431.57 5985.55,4450.59 5985.55,4470.59 5965.55,4490.59 5829.93,4490.59 v1@5819.93,4480.59 ; C20.1 6096.82,4607.91 6096.82,4637.91 6079.22,4655.51 U1.35 6010.52,4655.51 6000.52,4665.51 6000.52,4684.64 ; 5789.93,4560.82 5819.93,4530.82 v1@5819.93,4480.59 ; 5789.93,4560.82 5827.13,4598.03 5827.13,4658.03 ; 5827.13,4658.03 5830.52,4654.64 5970.52,4654.64 6000.52,4684.64
  Top Layer w10: LED1.1 3735.32,5307.04 LED2.1 3710.68,5182.06 3700.68,5182.06 3665.32,5146.7 3665.32,5091.83 3864.61,4892.54 4233.1,4892.54 D7.1 4316.19,4809.46 v1(4397.95,4809.46) 4397.95,4779.22 R28.2 ; U11.2 4348.45,4397.66 4348.45,4399.25 ; D6.2 4348.45,4399.25 ; D11.2 4466.4,3849.86 4514.87,3849.86 R44.2@4585.58,3920.57 ; R35.2 4478.36,4289.38 v1(4478.36,4314.4) 4443.01,4349.75 4397.94,4349.75 4348.45,4399.25 ; v1(4560.45,4819.46) 4570.45,4809.46 ULocker.2@4610.45,4809.46 ; v1(4568.36,4324.4) C1.2@4598.36,4354.4 ; C1.2 C1.2@4598.36,4354.4 ; R44.2 4583.36,3920.57 R44.2@4585.58,3920.57 ; C35.1 4602.17,4630.12 U7.5 4712.71,4610.12 4748.21,4610.12 ; ULocker.2 ULocker.2@4610.45,4809.46 ; R43.1 4688.08,3853.43 4688.08,3920.57 ; H1.1 4698.21,5010.06 4698.21,4850.12 ; Q3.2 4783.06,4163.79 4808.79,4163.79 ; C22.1 4804.69,4840.12 4748.21,4840.12 ; v1(4924.59,3922.76) R22.2 4956.29,3954.45 4956.29,4163.79 ; C27.1 4960.79,4763.94 4960.79,4614.02 ; Q2.2 Q2.2@5033.79,4283.79 ; C5.1 5335.46,4522.81 5337.61,4522.81 ; C18.1 5582.36,4547.56 5362.36,4547.56 5337.61,4522.81 ; v1(5689.37,4900.57) 5689.37,4760.57 5759.37,4690.57 5779.37,4690.57 5789.37,4700.57 ; C42.1 5862.21,4047.24 R45.2 5886.46,4162.05 5886.46,4243.46 ; 6101.89,4243.46 6101.89,4151.26 U12.1 ; H2.1 6357.01,4760.71 v1(6357.01,4586.06) 6347.01,4576.06 6347.01,4486.06 ; C20.1 6239.3,4465.43 C10.1@6301.38,4465.43 ; C10.1 C10.1@6301.38,4465.43 ; D9.1 6351.57,3795.93 6426.18,3795.93 ; C44.1 C44.1@6412.01,4210.04 ; R26.1 C41.1 6426.18,3646.65 6426.18,3795.93 ; D10.1 D10.1@6501.18,3795.93 ; C43.1 C43.1@6641.94,4047.45 ; R44.2@4585.58,3920.57 4688.08,3920.57 ; C1.2@4598.36,4354.4 4651.39,4301.36 4778.21,4301.36 4788.21,4311.36 4788.21,4610.12 ; ULocker.2@4610.45,4809.46 4615.75,4814.76 4632.86,4814.76 4668.21,4850.12 4698.21,4850.12 ; 4688.08,3920.57 4688.08,3973.07 4758.79,4043.79 4788.79,4043.79 4818.79,4073.79 4818.79,4153.79 4808.79,4163.79 ; 4698.21,4850.12 4738.21,4850.12 4748.21,4840.12 ; 4748.21,4610.12 4748.21,4840.12 ; 4748.21,4610.12 4788.21,4610.12 ; 4788.21,4610.12 4835.71,4610.12 4855.71,4630.12 U7.4 4921.81,4614.02 4960.79,4614.02 ; 4808.79,4163.79 4956.29,4163.79 ; 4956.29,4163.79 4973.79,4163.79 4983.79,4153.79 5083.79,4153.79 5093.79,4163.79 5093.79,4233.79 5083.79,4243.79 5073.79,4243.79 Q2.2@5033.79,4283.79 ; 4960.79,4614.02 C28.1 5082.68,4492.13 ; Q2.2@5033.79,4283.79 5072.68,4322.68 5072.68,4482.13 5082.68,4492.13 ; 5082.68,4492.13 C6.1 5306.93,4492.13 5337.61,4522.81 ; C10.1@6301.38,4465.43 6322.01,4486.06 6347.01,4486.06 ; 6347.01,4486.06 6362.01,4486.06 6412.01,4436.06 C44.1@6412.01,4210.04 ; C44.1@6412.01,4210.04 6502.16,4119.89 C9.1 6552.9,4118.16 6571.23,4118.16 C43.1@6641.94,4047.45 ; 6426.18,3795.93 D10.1@6501.18,3795.93 ; D10.1@6501.18,3795.93 v1(6501.18,3890.94) 6541.18,3890.94 6611.89,3961.66 6611.89,4017.4 C43.1@6641.94,4047.45
  Bottom Layer w9.57: v1(5569.93,4440.82) 5599.93,4410.82 5759.93,4410.82 v1(5819.93,4470.82) ; v1(6254.51,4286.06) 6364.51,4396.06 6364.51,4576.06 v1@6354.51,4586.06
  Bottom Layer w10: v1(4397.95,4809.46) 4407.95,4819.46 U9.5@4473.85,4819.46 ; U8.4 4480.09,3777.78 C37.2@4813.22,3777.78 ; U9.5 U9.5@4473.85,4819.46 ; v1(4478.36,4314.4) 4488.36,4304.4 4548.36,4304.4 v1(4568.36,4324.4) ; v1(4560.45,4819.46) U9.5@4473.85,4819.46 ; C37.2 C37.2@4813.22,3777.78 ; v1(4924.59,3922.76) 4924.59,3889.15 C37.2@4813.22,3777.78 ; 4GGPS.4 5689.37,5014.17 v1(5689.37,4900.57) ; U3.3 6343.08,4586.06 6354.51,4586.06 v1(6357.01,4586.06) ; v1(6501.18,3890.94) C40.2
LOCKER1(RED): C36.2 U9.7 ULocker.6 | length 547.8
  Top Layer w10: ULocker.6 4532.06,4755.54 ; v1(4552.06,4775.54) 4532.06,4755.54 ; C36.2 4666.07,4689.69 4597.91,4689.69 4532.06,4755.54
  Bottom Layer w10: U9.7 4489.89,4960.9 4516.7,4960.9 4552.06,4925.54 4552.06,4875.54 4587.41,4840.19 4587.41,4810.9 v1(4552.06,4775.54)
LOCKER2(BLACK): C36.1 U9.6 ULocker.4 | length 809.6
  Top Layer w10: v1(4397.91,4894.49) 4447.91,4844.49 ULocker.4 ; v1(4660.41,4794.49) 4692.13,4794.49 C36.1
  Bottom Layer w10: v1(4397.91,4894.49) v1@4400.41,4894.49 ; U9.6 4463.39,4894.49 v1@4400.41,4894.49 ; v1(4660.41,4794.49) 4575.77,4879.13 4575.77,4989.13 4540.41,5024.49 4410.41,5024.49 4400.41,5014.49 v1@4400.41,4894.49
NRST: U1.7
OSC32_IN: C27.2 U1.3 X5.1 | length 875.6
  Top Layer w9.57: C27.2 5161.42,4885.83 5440.63,4885.83 5500.63,4825.83 v1(5500.63,4765.83) ; v1(5590.63,4675.83) 5595.28,4671.18 5625.28,4671.18 5660.63,4635.83 U1.3
  Top Layer w10: X5.1 5102.36,4789.38 C27.2
  Bottom Layer w9.57: v1(5500.63,4765.83) v1(5590.63,4675.83)
OSC32_OUT: C28.2 U1.4 X5.2 | length 772.2
  Top Layer w9.57: C28.2 5131.23,4564.3 5143.07,4576.14 5250.63,4576.14 5270.63,4556.14 v1(5270.63,4546.14) ; v1(5650.63,4596.14) 5670.63,4616.14 U1.4
  Top Layer w10: X5.2 5131.23,4567.58 C28.2@5131.23,4564.3
  Bottom Layer w9.57: v1(5270.63,4546.14) 5320.63,4596.14 v1(5650.63,4596.14)
OSC_IN: C5.2 U1.5 X2.2 | length 681.6
  Top Layer w9.57: X2.2 5426.93,4736.46 v1(5570.63,4736.46) ; U1.5 5740.63,4596.46 v1(5760.63,4616.46)
  Top Layer w10: C5.2 5293.31,4757.88 X2.2
  Bottom Layer w9.57: v1(5570.63,4736.46) 5690.63,4616.46 v1(5760.63,4616.46)
OSC_OUT: C6.2 U1.6 X2.1 | length 829.1
  Top Layer w9.57: X2.1 5434.81,4436.77 v1(5530.63,4436.77) ; U1.6 5750.63,4576.77 v1(5760.63,4566.77)
  Top Layer w10: C6.2 5251.73,4519.93 v1(5293.79,4519.93)
  Bottom Layer w9.57: v1(5530.63,4436.77) 5533.79,4439.93 5660.63,4566.77 v1(5760.63,4566.77)
  Bottom Layer w10: v1(5293.79,4519.93) 5373.79,4439.93 v1@5533.79,4439.93
PA0: C42.2 R45.1 R46.1 U1.10 | length 673.3
  Top Layer w9.57: R46.1 5606.32,4258.03 5606.32,4269.31 5606.32,4408.03 5660.63,4462.34 5660.63,4478.03 5680.63,4498.03 U1.10
  Top Layer w10: 5606.32,4269.31 5666.32,4269.31 5701.68,4233.95 5701.68,4219.58 R45.1 5783.47,4047.24 C42.2
PA1: U1.11 U3.5 | length 731.9
  Top Layer w9.57: U1.11 5750.63,4478.35 v1(5760.63,4488.35)
  Bottom Layer w9.57: v1(5760.63,4488.35) 5800.63,4488.35 5835.99,4523.7 5885.99,4523.7 6168.83,4806.55 6267.97,4806.55 U3.5
PA2: 4GGPS.2 U1.12 | length 761.2
  Top Layer w9.57: U1.12 5710.63,4448.66 v1(5720.63,4438.66)
  Bottom Layer w9.57: 4GGPS.2 5790.63,4712.91 5790.63,4558.66 5720.63,4488.66 v1(5720.63,4438.66)
PA3: 4GGPS.3 U1.13 | length 730.2
  Top Layer w9.57: U1.13 5769.68,4449.61 5789.68,4469.61 v1(5789.68,4519.61)
  Bottom Layer w9.57: 4GGPS.3 5597.55,5005.99 5597.55,4931.74 5809.68,4719.61 5809.68,4539.61 v1(5789.68,4519.61)
PA4: U1.14 ULocker.3 | length 1807.8
  Top Layer w9.57: ULocker.3 4608.07,5014.49 4658.07,5064.49 4808.07,5064.49 4843.43,5029.13 4843.43,4999.13 4878.78,4963.78 4908.78,4963.78 v1(4938.07,4934.49) ; v1(5738.07,4354.49) 5774.25,4354.49 5789.37,4369.61 U1.14
  Bottom Layer w9.57: v1(4938.07,4934.49) 4938.07,4784.49 5358.07,4364.49 5728.07,4364.49 v1(5738.07,4354.49)
PA5: R39.2 U1.15 U9.4 | length 1607
  Top Layer w9.57: R39.2 5665.26,4358.36 5694.01,4329.61 5779.05,4329.61 5809.05,4359.61 U1.15
  Top Layer w10: v1(5635.26,4338.36) 5655.26,4358.36 R39.2@5665.26,4358.36
  Bottom Layer w10: U9.4 4929.53,4744.09 5335.26,4338.36 v1(5635.26,4338.36)
PA6: U1.16 ULocker.1 | length 1483.2
  Top Layer w9.57: ULocker.1 4608.07,4759.69 v1(4648.07,4719.69) ; v1(4828.07,4689.69) 4848.07,4669.69 v1(4898.07,4669.69) ; v1(5648.07,4309.69) 5788.07,4309.69 5828.74,4350.36 U1.16
  Bottom Layer w9.57: v1(4648.07,4719.69) 4798.07,4719.69 v1(4828.07,4689.69) ; v1(4898.07,4669.69) 5258.07,4309.69 v1(5648.07,4309.69)
PA7: R35.1 U1.17 U11.1 | length 1804.7
  Top Layer w9.57: R35.1 4418.42,4308.19 v1(4418.42,4309.61) ; U1.17 5848.42,4359.61 v1(5858.42,4349.61)
  Top Layer w10: U11.1 4293.31,4267.72 R35.1
  Bottom Layer w9.57: v1(4418.42,4309.61) 4449.14,4278.9 5787.71,4278.9 v1(5858.42,4349.61)
PA8: U1.29
PA9/USART1_TX: R29.1 U1.30 | length 1102.3
  Top Layer w9.57: R29.1 5312.91,4187.09 v1(5315.27,4187.09) ; U1.30 6075.27,4557.09 6095.27,4537.09 6095.27,4447.09 v1(6085.27,4437.09)
  Bottom Layer w9.57: v1(5315.27,4187.09) 5317.79,4189.6 5837.79,4189.6 v1(6085.27,4437.09)
PA10/USART1_RX: R31.1 U1.31 | length 1025.7
  Top Layer w9.57: R31.1 5122.6,4416.77 v1(5345.27,4416.77) ; v1(5915.27,4516.77) 5975.27,4576.77 U1.31
  Bottom Layer w9.57: v1(5345.27,4416.77) 5375.27,4386.77 5785.27,4386.77 v1(5915.27,4516.77)
PA13/SWDIO: H1.3 U1.34 U9.2 | length 2644.3
  Top Layer w9.57: v1(5946.46,4624.31) 5957.98,4635.83 U1.34
  Bottom Layer w9.57: 4966.46,5084.31 5686.46,5084.31 5736.46,5034.31 5736.46,4854.31 5913.23,4677.53 5913.23,4657.53 v1(5946.46,4624.31)
  Bottom Layer w10: U9.2 4435.83,4621.26 4405.83,4621.26 4370.47,4656.61 4370.47,5011.81 4480.47,5121.81 4946.46,5121.81 4966.46,5101.81 4966.46,5084.31 4966.46,5081.81 H1.3
PA14/SWCLK: H1.2 U1.37 U9.3 | length 2264.1
  Top Layer w9.57: v1(4936.46,5089.31) 5881.16,5089.31 5941.16,5029.31 v1(5941.16,4979.31) ; v1(5981.16,4819.31) 5986.22,4814.25 U1.37
  Top Layer w10: v1(4856.46,4711.81) v1(4856.46,4771.81)
  Bottom Layer w9.57: H1.2@4796.46,5009.31 4867.17,5080.02 4927.17,5080.02 v1(4936.46,5089.31) ; v1(5941.16,4979.31) 5941.16,4859.31 v1(5981.16,4819.31)
  Bottom Layer w10: U9.3 4840,4665.35 4856.46,4681.81 v1(4856.46,4711.81) ; H1.2 4796.46,5009.31 4796.46,4831.81 v1(4856.46,4771.81)
PA15: U1.38
PB0: R40.1 U1.18 | length 1799.8
  Top Layer w9.57: R40.1 4386.46,4189.61 v1(4408.11,4189.61) ; U1.18 5868.11,4429.61 v1(5888.11,4449.61)
  Bottom Layer w9.57: v1(4408.11,4189.61) 4458.11,4239.61 5788.11,4239.61 5888.11,4339.61 v1(5888.11,4449.61)
PB1: D11.1 R42.2 R43.2 U1.19 | length 1750.6
  Top Layer w9.57: R42.2 4798.04,3969.17 4828.48,3999.61 v1(4867.79,3999.61) ; U1.19 5887.79,4369.61 v1(5917.79,4339.61)
  Top Layer w10: D11.1 4527.32,3801.02 4714.41,3801.02 R43.2 4798.04,3884.65 R42.2@4798.04,3969.17
  Bottom Layer w9.57: v1(4867.79,3999.61) 5087.79,4219.61 5797.79,4219.61 v1(5917.79,4339.61)
PB3: U1.39
PB4: U1.40
PB5: U1.41
PB6: 4GGPS.6 U1.42 | length 287.1
  Top Layer w9.57: v1(5883.86,4804.25) 5887.79,4800.31 U1.42
  Bottom Layer w9.57: v1(5883.86,4804.25) 4GGPS.6
PB7: 4GGPS.1 U1.43 | length 780.4
  Top Layer w9.57: v1(5868.11,4684.25) U1.43
  Bottom Layer w9.57: 4GGPS.1 5428.42,5064.25 5608.11,5064.25 5628.11,5044.25 5628.11,4924.25 v1(5868.11,4684.25)
PB8: H2.3 U1.45 | length 615.7
  Top Layer w9.57: U1.45 5828.74,4764.25 5848.74,4784.25 v1(5858.74,4784.25)
  Bottom Layer w9.57: v1(5858.74,4784.25) 5868.74,4774.25 6060.47,4774.25 H2.3
PB9: H2.4 U1.46 | length 828.3
  Top Layer w9.57: v1(5799.05,4824.25) 5809.05,4814.25 U1.46 ; v1(5859.05,4904.25) 5894.41,4939.6 5934.41,4939.6 6059.05,5064.25 6353.47,5064.25 H2.4
  Bottom Layer w9.57: v1(5799.05,4824.25) 5799.05,4844.25 v1(5859.05,4904.25)
PB10: U1.21 U3.1 | length 477.8
  Top Layer w9.57: v1(5917.16,4459.61) 5927.16,4449.61 U1.21
  Bottom Layer w9.57: v1(5917.16,4459.61) 5942.92,4433.86 5992.92,4433.86 6022.92,4463.86 6265.28,4463.86 U3.1
PB11: U1.22 U3.2 | length 433.3
  Top Layer w9.57: U1.22 5946.85,4449.61 v1(5956.85,4459.61)
  Bottom Layer w9.57: v1(5956.85,4459.61) 5992.21,4494.96 6256.39,4494.96 U3.2
PB12: U1.25
PB13: U1.26
PB14: U1.27
PB15: U1.28
PC13: R13.2 U1.2 | length 1489.3
  Top Layer w9.57: R13.2 4616.38,5088.82 4867.32,5088.82 4897.79,5058.35 5247.79,5058.35 5389.21,4916.93 5439.21,4916.93 5580.63,4775.51 v1(5580.63,4765.51) ; v1(5630.63,4715.51) 5635.28,4710.86 5635.28,4690.86 5670.63,4655.51 U1.2
  Bottom Layer w9.57: v1(5580.63,4765.51) v1(5630.63,4715.51)
SPK1: Q3.3 U8.7 | length 285.9
  Top Layer w10: v1(4650.79,4083.3) 4654.17,4083.3 Q3.3
  Bottom Layer w10: U8.7 4610.79,4043.3 v1(4650.79,4083.3)
USB_D+_PA12: U1.33
USB_D-_PA11: U1.32
VBAT: U1.1
VDC+: C37.1 Q1.2 Q4.2 R17.2 R37.1 R42.1 U8.1 | length 2667.7
  Top Layer w10: Q4.2 4234.25,3935.43 4387.46,3782.23 4731.66,3782.23 4751.66,3802.23 4801.66,3802.23 4901.66,3902.23 ; R42.1 4794.74,4025.19 4893.7,4025.19 ; R37.1 4893.7,4025.19 ; v1(4981.21,3733.18) R17.2 5045.96,3797.93 ; Q1.2 5132.58,3884.55 5045.96,3797.93 ; 4893.7,4025.19 4893.7,3910.19 4901.66,3902.23 ; 4901.66,3902.23 5005.96,3797.93 5045.96,3797.93
  Bottom Layer w10: U8.1 4599.9,3421.75 C37.1@4811.51,3421.75 ; C37.1 C37.1@4811.51,3421.75 ; v1(4981.21,3733.18) 4981.21,3591.45 C37.1@4811.51,3421.75
WHEEL: R46.2 U8.3 | length 1453.1
  Top Layer w10: v1(5240.79,4058.34) 5465.96,4058.34 R46.2
  Bottom Layer w10: U8.3 4500.79,3728.34 4560.79,3668.34 4850.79,3668.34 v1(5240.79,4058.34)
pads on no net: Q1.1 U4.1 U8.9 U8.10 U9.8 U9.9 U12.2
copper on no net: | length 405.5
  Top Layer w10: 5220.86,3627.26 5308.13,3714.53 v1(5382.19,3714.53) ; v1(5452.19,3784.53) 5522.19,3854.53 5532.19,3854.53
  Bottom Layer w10: v1(5382.19,3714.53) v1(5452.19,3784.53)

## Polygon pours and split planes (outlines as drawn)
no net on Top Layer (solid, remove dead copper): 7602.36,5840.39 7612.36,5840.39 7612.36,5850.39 7602.36,5850.39
GND on Top Layer (solid, remove dead copper, pour order 2): 4019.68,3283.46 6787.4,3283.46 6787.4,5125.98 4019.68,5125.98
GND on Bottom Layer (solid, remove dead copper, pour order 4): 4007.87,3262.6 6811.02,3262.6 6811.02,5149.61 4007.87,5149.61

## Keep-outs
Board Outline Layer:
  lines w10: 3000,3000 6913.39,3000 6913.39,5519.69 3000,5519.69 3000,3000
Multi-Layer:
  circle w10: c3322.83,4889.76 r98.43
  circle w10: c3322.83,3610.24 r98.43
  circle w10: c3322.83,5204.72 r98.43
  circle w10: c3322.83,3314.96 r98.43
  circle w10: c3590.55,4681.1 r82.68
  circle w10: c3614.17,4149.61 r78.74
  circle w10: c3614.17,3838.58 r94.49
  circle w10: c3145.67,4681.1 r82.68
  circle w10: c3169.29,3838.58 r94.49
  circle w10: c3169.29,4149.61 r78.74
  circle w10: c6740.16,5354.33 r98.43
  circle w10: c6720.47,3133.86 r98.43
  circle w10: c3980.32,5291.34 r78.74
  circle w10: c4007.87,3240.16 r78.74
  circle w10: c7586.62,4145.67 r78.74
  circle w10: c5311.02,5334.65 r78.74
  region: 3224.41,4889.76 3421.26,4889.76 3421.26,5204.72 3224.41,5204.72
  region: 3224.41,3295.28 3421.26,3295.28 3421.26,3610.24 3224.41,3610.24
  region: 3141.73,4597.91 3594.49,4597.91 3594.49,4763.37 3141.73,4763.37
  region: 3155.51,4070.82 3608.27,4070.82 3608.27,4228.4 3155.51,4228.4
  region: 3167.32,3744.04 3620.08,3744.04 3620.08,3933.12 3167.32,3933.12
  region: 6604.87,4273.8 6938.98,4273.8 6938.98,4993.12 6604.87,4993.12

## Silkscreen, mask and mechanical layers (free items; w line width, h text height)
Mechanical Layer:
  circle w1: c3322.83,4889.76 r98.43
  circle w1: c3322.83,3610.24 r98.43
  circle w1: c3322.83,5204.72 r98.43
  circle w1: c3322.83,3314.96 r98.43
  circle w1: c3590.55,4681.1 r82.68
  circle w1: c3614.17,4149.61 r78.74
  circle w1: c3614.17,3838.58 r94.49
  circle w1: c3145.67,4681.1 r82.68
  circle w1: c3169.29,3838.58 r94.49
  circle w1: c3169.29,4149.61 r78.74
  circle w1: c6740.16,5354.33 r98.43
  circle w1: c6720.47,3133.86 r98.43
  circle w1: c3980.32,5291.34 r78.74
  circle w1: c4007.87,3240.16 r78.74
  circle w1: c7586.62,4145.67 r78.74
  circle w1: c5311.02,5334.65 r78.74
  lines w1: 3141.73,4597.91 3594.49,4597.91 3594.49,4763.37 3141.73,4763.37 3141.73,4597.91 ; 3155.51,4070.82 3608.27,4070.82 3608.27,4228.4 3155.51,4228.4 3155.51,4070.82 ; 3167.32,3744.04 3620.08,3744.04 3620.08,3933.12 3167.32,3933.12 3167.32,3744.04 ; 3224.41,3295.28 3421.26,3295.28 3421.26,3610.24 3224.41,3610.24 3224.41,3295.28 ; 3224.41,4889.76 3421.26,4889.76 3421.26,5204.72 3224.41,5204.72 3224.41,4889.76 ; 6604.87,4273.8 6938.98,4273.8 6938.98,4993.12 6604.87,4993.12 6604.87,4273.8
